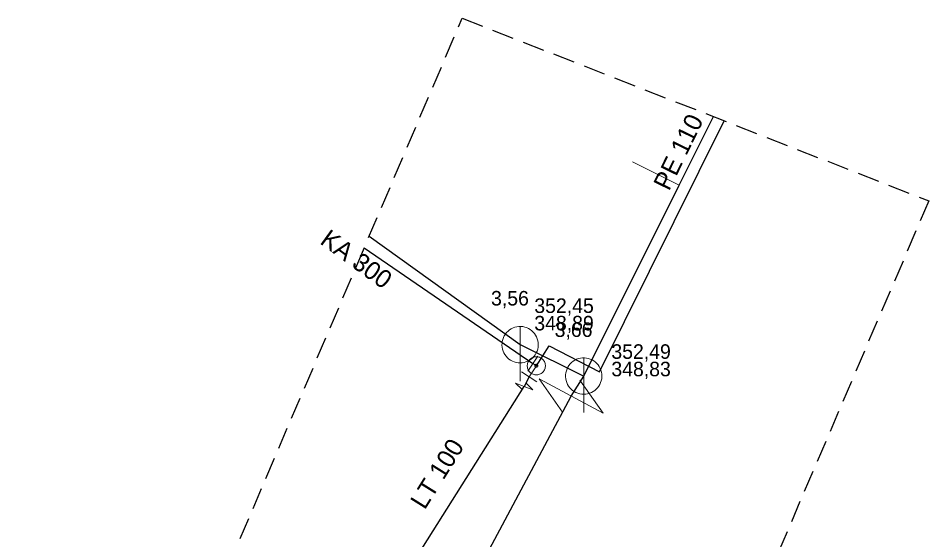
# Model space of a CAD drawing. Extents: x -688691 to -688449, y -974248 to -973966.
# Drawn here: x -688499.2 to -688449.1, y -973994.2 to -973965.6 of the extents above; entities that cross this region are included whole.
import ezdxf

# ---------------------------------------------------------------- set-up
doc = ezdxf.new("R2010")
doc.units = 0
doc.header["$LTSCALE"] = 0.4
doc.linetypes.add('MEDIUM_DASHED', pattern=[4.5, 3, -1.5])
for name, color, linetype, lineweight in [('1', 7, 'MEDIUM_DASHED', 25), ('11', 7, 'Continuous', 13), ('14', 7, 'Continuous', 25), ('17', 7, 'Continuous', 25), ('22', 7, 'Continuous', 13), ('31', 7, 'Continuous', 13), ('34', 7, 'Continuous', 13), ('47', 7, 'Continuous', 13)]:
    doc.layers.add(name, color=color, linetype=linetype, lineweight=lineweight)

msp = doc.modelspace()

# ---------------------------------------------------------------- linework, layer by layer
at = {"layer": '1'}
msp.add_lwpolyline([(-688492.642, -974007.422), (-688474.778, -973965.553), (-688449.099, -973975.602), (-688472.545, -974030.309), (-688492.642, -974033.659), (-688555.165, -974021.936), (-688650.066, -974071.061), (-688624.387, -974128.002), (-688613.222, -974120.745), (-688593.125, -974162.055), (-688604.29, -974165.404), (-688581.96, -974212.855), (-688565.213, -974206.156), (-688558.514, -974230.719), (-688607.64, -974248.024), (-688622.154, -974231.277), (-688607.64, -974225.136), (-688626.62, -974194.433), (-688691.376, -974059.338), (-688565.213, -973995.698), (-688544, -974002.397)], close=True, dxfattribs=at)
at = {"layer": '11'}
msp.add_line((-688465.399, -973973.449), (-688462.833, -973974.734), dxfattribs=at)
at = {"layer": '14'}
for p, q in [((-688479.89, -973977.536), (-688471.59, -973983.51)), ((-688471.59, -973983.51), (-688468.09, -973985.239)), ((-688468.78, -973986.34), (-688468.09, -973985.239))]:
    msp.add_line(p, q, dxfattribs=at)
at = {"layer": '14', "lineweight": 13}
for p in [(-688471.09, -973985.28), (-688470.89, -973984.55)]:
    msp.add_line(p, (-688470.697, -973984.674), dxfattribs=at)
at = {"layer": '14'}
for points in [[(-688468.09, -973985.239), (-688462.833, -973974.734), (-688460.948, -973970.965)], [(-688486.318, -974032.605), (-688486.197, -974018.952), (-688468.78, -973986.34)]]:
    msp.add_lwpolyline(points, dxfattribs=at)
at = {"layer": '17'}
for p, q in [((-688480.166, -973978.183), (-688470.89, -973984.55)), ((-688471.09, -973985.28), (-688471.37, -973985.809))]:
    msp.add_line(p, q, dxfattribs=at)
for points in [[(-688470.697, -973984.674), (-688469.989, -973983.579), (-688467.219, -973985), (-688460.368, -973971.192)], [(-688463.974, -974010.312), (-688468.81, -974004.393), (-688475.474, -973996.658), (-688477.442, -973995.438), (-688471.37, -973985.809)]]:
    msp.add_lwpolyline(points, dxfattribs=at)
at = {"layer": '22'}
for p, q in [((-688471.59, -973985.51), (-688471.589, -973982.51)), ((-688468.09, -973987.239), (-688468.089, -973984.239))]:
    msp.add_line(p, q, dxfattribs=at)
for points in [[(-688470.59, -973983.51), (-688470.595, -973983.401), (-688470.613, -973983.293), (-688470.643, -973983.187), (-688470.683, -973983.086), (-688470.735, -973982.989), (-688470.797, -973982.899), (-688470.869, -973982.816), (-688470.949, -973982.742), (-688471.037, -973982.676), (-688471.131, -973982.621), (-688471.231, -973982.576), (-688471.336, -973982.543), (-688471.443, -973982.521), (-688471.552, -973982.511), (-688471.662, -973982.513), (-688471.77, -973982.527), (-688471.877, -973982.552), (-688471.98, -973982.589), (-688472.078, -973982.638), (-688472.17, -973982.696), (-688472.256, -973982.765), (-688472.333, -973982.842), (-688472.402, -973982.928), (-688472.461, -973983.02), (-688472.509, -973983.118), (-688472.546, -973983.221), (-688472.572, -973983.328), (-688472.586, -973983.436), (-688472.589, -973983.546), (-688472.579, -973983.655), (-688472.558, -973983.762), (-688472.524, -973983.866), (-688472.48, -973983.966), (-688472.425, -973984.061), (-688472.359, -973984.149), (-688472.285, -973984.229), (-688472.202, -973984.301), (-688472.112, -973984.363), (-688472.016, -973984.415), (-688471.914, -973984.456), (-688471.809, -973984.486), (-688471.701, -973984.504), (-688471.591, -973984.51), (-688471.482, -973984.504), (-688471.374, -973984.486), (-688471.269, -973984.457), (-688471.167, -973984.416), (-688471.07, -973984.364), (-688470.98, -973984.302), (-688470.897, -973984.231), (-688470.822, -973984.151), (-688470.757, -973984.063), (-688470.701, -973983.969), (-688470.657, -973983.869), (-688470.623, -973983.765), (-688470.601, -973983.657), (-688470.591, -973983.548)], [(-688467.09, -973985.239), (-688467.095, -973985.13), (-688467.113, -973985.022), (-688467.143, -973984.916), (-688467.183, -973984.815), (-688467.235, -973984.718), (-688467.297, -973984.628), (-688467.369, -973984.545), (-688467.449, -973984.471), (-688467.537, -973984.405), (-688467.631, -973984.35), (-688467.731, -973984.305), (-688467.836, -973984.272), (-688467.943, -973984.25), (-688468.052, -973984.24), (-688468.162, -973984.242), (-688468.27, -973984.256), (-688468.377, -973984.281), (-688468.48, -973984.318), (-688468.578, -973984.367), (-688468.67, -973984.425), (-688468.756, -973984.494), (-688468.833, -973984.571), (-688468.902, -973984.657), (-688468.961, -973984.749), (-688469.009, -973984.847), (-688469.046, -973984.95), (-688469.072, -973985.057), (-688469.086, -973985.165), (-688469.089, -973985.275), (-688469.079, -973985.384), (-688469.058, -973985.491), (-688469.024, -973985.595), (-688468.98, -973985.695), (-688468.925, -973985.79), (-688468.859, -973985.878), (-688468.785, -973985.958), (-688468.702, -973986.03), (-688468.612, -973986.092), (-688468.516, -973986.144), (-688468.414, -973986.185), (-688468.309, -973986.215), (-688468.201, -973986.233), (-688468.091, -973986.239), (-688467.982, -973986.233), (-688467.874, -973986.215), (-688467.769, -973986.186), (-688467.667, -973986.145), (-688467.57, -973986.093), (-688467.48, -973986.031), (-688467.397, -973985.96), (-688467.322, -973985.88), (-688467.257, -973985.792), (-688467.201, -973985.698), (-688467.157, -973985.598), (-688467.123, -973985.494), (-688467.101, -973985.386), (-688467.091, -973985.277)]]:
    msp.add_lwpolyline(points, close=True, dxfattribs=at)
at = {"layer": '31'}
msp.add_lwpolyline([(-688469.25, -973987.222), (-688470.543, -973985.398), (-688467.015, -973987.282), (-688468.308, -973985.458)], dxfattribs=at)
at = {"layer": '34'}
for p, q in [((-688470.607, -973984.137), (-688471.173, -973984.961)), ((-688471.51, -973985.008), (-688470.67, -973985.552))]:
    msp.add_line(p, q, dxfattribs=at)
at = {"layer": '47'}
msp.add_line((-688471.845, -973985.625), (-688471.477, -973985.979), dxfattribs=at)
for points in [[(-688470.425, -973984.254), (-688470.47, -973984.228), (-688470.518, -973984.206), (-688470.568, -973984.191), (-688470.619, -973984.18), (-688470.671, -973984.174), (-688470.724, -973984.175), (-688470.775, -973984.181), (-688470.827, -973984.192), (-688470.876, -973984.207), (-688470.924, -973984.228), (-688470.97, -973984.255), (-688471.012, -973984.286), (-688471.051, -973984.321), (-688471.086, -973984.36), (-688471.116, -973984.402), (-688471.142, -973984.447), (-688471.164, -973984.495), (-688471.18, -973984.546), (-688471.19, -973984.596), (-688471.196, -973984.648), (-688471.195, -973984.701), (-688471.19, -973984.753), (-688471.179, -973984.804), (-688471.163, -973984.854), (-688471.142, -973984.901), (-688471.115, -973984.947), (-688471.084, -973984.989), (-688471.049, -973985.028), (-688471.01, -973985.063), (-688470.968, -973985.093), (-688470.923, -973985.119), (-688470.875, -973985.141), (-688470.825, -973985.157), (-688470.774, -973985.167), (-688470.722, -973985.173), (-688470.67, -973985.173), (-688470.617, -973985.168), (-688470.566, -973985.157), (-688470.516, -973985.14), (-688470.469, -973985.119), (-688470.423, -973985.092), (-688470.381, -973985.062), (-688470.342, -973985.026), (-688470.307, -973984.987), (-688470.277, -973984.945), (-688470.251, -973984.9), (-688470.229, -973984.852), (-688470.213, -973984.803), (-688470.203, -973984.751), (-688470.197, -973984.699), (-688470.197, -973984.647), (-688470.203, -973984.595), (-688470.214, -973984.544), (-688470.23, -973984.494), (-688470.251, -973984.446), (-688470.278, -973984.4), (-688470.308, -973984.359), (-688470.344, -973984.319), (-688470.383, -973984.284)], [(-688470.652, -973984.605), (-688470.66, -973984.6), (-688470.667, -973984.597), (-688470.675, -973984.594), (-688470.683, -973984.593), (-688470.692, -973984.592), (-688470.701, -973984.592), (-688470.71, -973984.592), (-688470.718, -973984.594), (-688470.726, -973984.597), (-688470.734, -973984.601), (-688470.742, -973984.605), (-688470.748, -973984.61), (-688470.754, -973984.616), (-688470.76, -973984.621), (-688470.765, -973984.629), (-688470.77, -973984.637), (-688470.773, -973984.644), (-688470.776, -973984.652), (-688470.777, -973984.66), (-688470.778, -973984.669), (-688470.778, -973984.678), (-688470.778, -973984.687), (-688470.776, -973984.695), (-688470.773, -973984.704), (-688470.769, -973984.711), (-688470.765, -973984.719), (-688470.76, -973984.725), (-688470.754, -973984.731), (-688470.749, -973984.737), (-688470.741, -973984.742), (-688470.733, -973984.747), (-688470.726, -973984.75), (-688470.718, -973984.753), (-688470.71, -973984.754), (-688470.701, -973984.755), (-688470.693, -973984.756), (-688470.683, -973984.755), (-688470.675, -973984.753), (-688470.666, -973984.75), (-688470.659, -973984.746), (-688470.651, -973984.742), (-688470.645, -973984.737), (-688470.639, -973984.731), (-688470.633, -973984.726), (-688470.628, -973984.718), (-688470.623, -973984.71), (-688470.62, -973984.703), (-688470.617, -973984.695), (-688470.616, -973984.687), (-688470.615, -973984.678), (-688470.614, -973984.67), (-688470.615, -973984.66), (-688470.617, -973984.652), (-688470.62, -973984.644), (-688470.624, -973984.636), (-688470.628, -973984.628), (-688470.633, -973984.622), (-688470.639, -973984.616), (-688470.644, -973984.61)]]:
    msp.add_lwpolyline(points, close=True, dxfattribs=at)
msp.add_lwpolyline([(-688471.845, -973985.625), (-688470.894, -973985.992), (-688471.262, -973985.638)], dxfattribs=at)

# ---------------------------------------------------------------- texts
at = {"layer": '1'}
for s, rotation, p in [('PE 110', 64, (-688463.397, -973975.098)), ('KA 300', 324, (-688482.662, -973977.918)), ('LT 100', 58, (-688476.839, -973992.635))]:
    msp.add_text(s, height=1, rotation=rotation, dxfattribs=at).set_placement(p)
for s, p in [('3,56', (-688473.189, -973981.357)), ('3,66', (-688469.69, -973983.087))]:
    msp.add_text(s, height=0.8, dxfattribs=at).set_placement(p)
at = {"layer": '22'}
for s, p in [('352,45', (-688470.808, -973981.767)), ('348,89', (-688470.808, -973982.727)), ('352,49', (-688466.568, -973984.291)), ('348,83', (-688466.568, -973985.251))]:
    msp.add_text(s, height=0.8, dxfattribs=at).set_placement(p)

doc.saveas('drawing.dxf')
